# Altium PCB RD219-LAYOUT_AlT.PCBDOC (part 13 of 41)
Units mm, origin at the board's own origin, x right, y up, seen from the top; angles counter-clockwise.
Board outline 209.75 x 159.97 mm, 2 copper layers (TOP, BOTTOM), stack 0 mm thick; 398 components, 199 nets, 1469 pads, 0 vias.
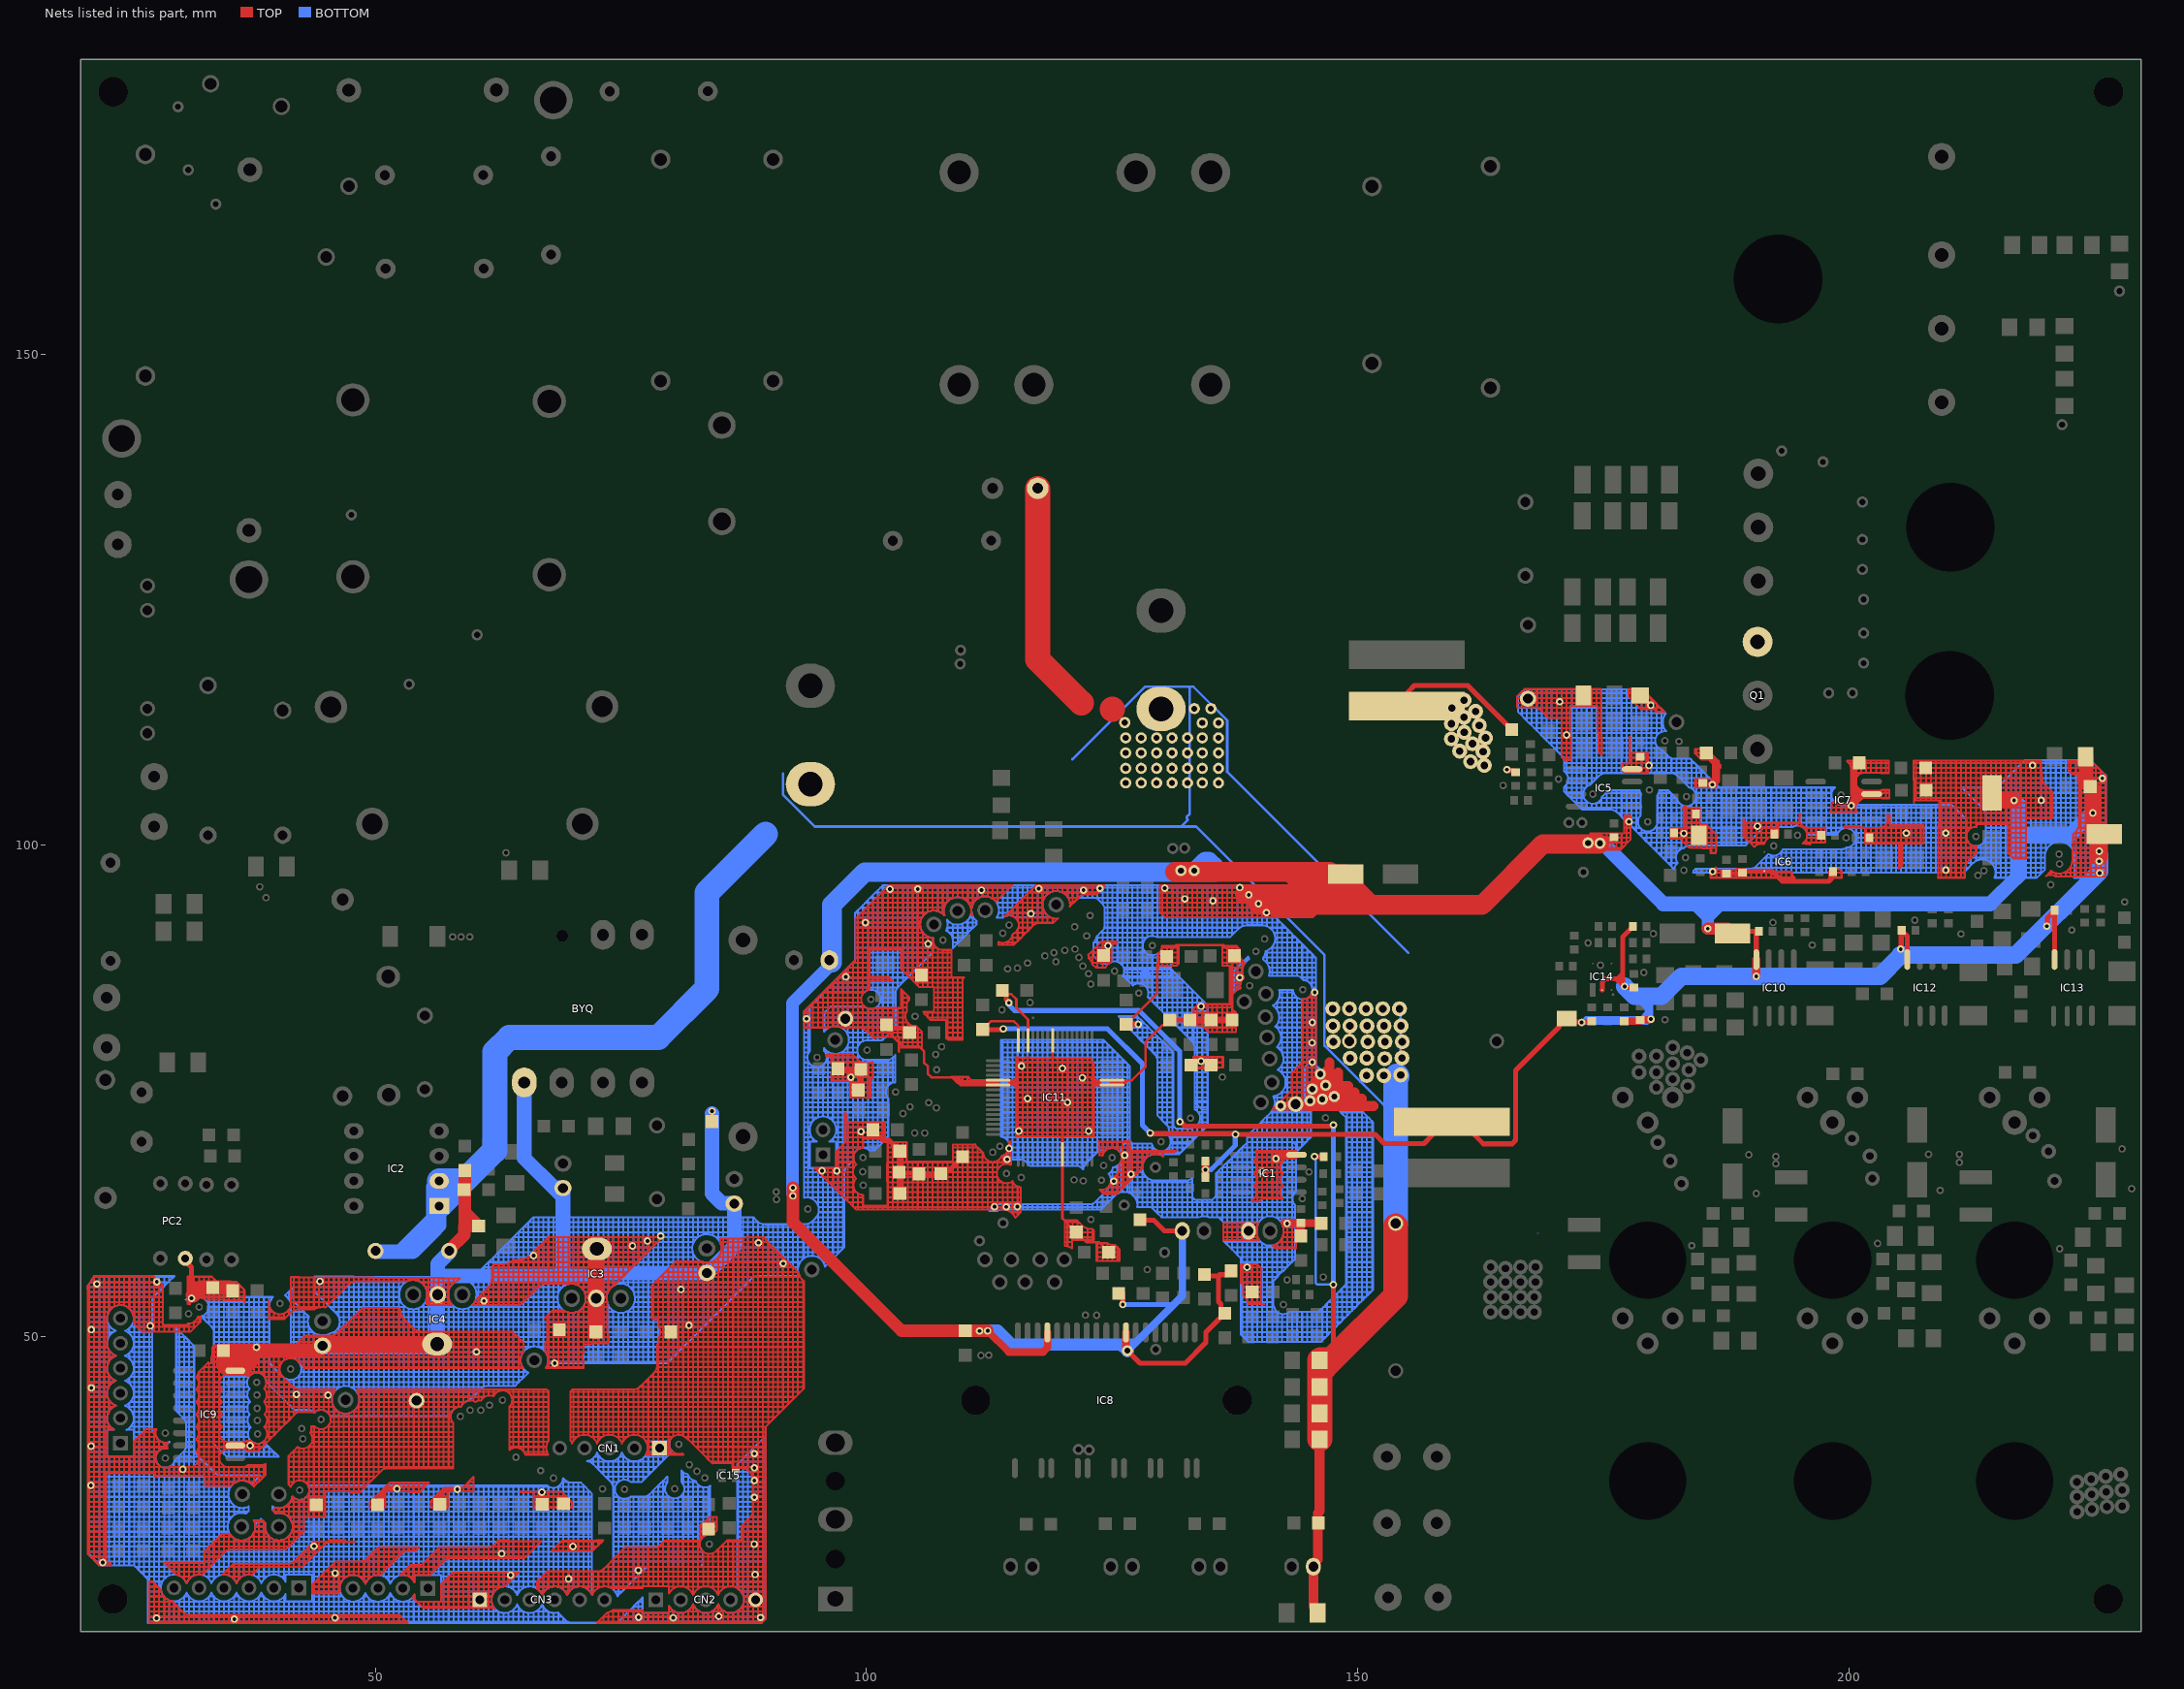
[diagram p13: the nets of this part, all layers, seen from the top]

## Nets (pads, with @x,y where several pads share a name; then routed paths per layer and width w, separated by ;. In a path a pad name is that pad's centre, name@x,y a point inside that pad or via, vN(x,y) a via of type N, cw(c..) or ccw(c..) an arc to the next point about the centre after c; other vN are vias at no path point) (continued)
GND: (continued)
  TOP w0.203: 102.677,80.96 103.185,80.96 ; 102.677,80.96 102.677,81.397 C98.2@102.677,81.468 ; C98.2@102.677,81.468 103.185,81.468 ; C98.2@102.677,81.468 C98.2@102.677,81.976 ; C98.2@102.677,81.976 102.677,82.484 ; C98.2@102.677,81.976 103.185,81.976 ; 102.677,82.484 102.677,82.992 ; 102.677,82.484 103.185,82.484 ; 102.677,82.992 103.185,82.992 ; 102.677,82.992 102.677,83.441 ; 102.677,83.441 103.185,83.441 ; 102.677,89.401 102.677,89.596 ; 102.677,89.401 103.185,89.401 ; 102.677,89.596 102.677,90.104 ; 102.677,89.596 103.185,89.596 ; 102.677,90.104 102.677,90.612 ; 102.677,90.104 103.185,90.104 ; 102.677,90.612 102.677,91.12 ; 102.677,90.612 103.185,90.612 ; 102.677,91.12 102.677,91.628 ; 102.677,91.12 103.185,91.12 ; 102.677,91.628 102.677,92.136 ; 102.677,91.628 103.185,91.628 ; 102.677,92.136 102.677,92.644 ; 102.677,92.136 103.185,92.136 ; 102.677,92.644 102.677,93.152 ; 102.677,92.644 103.185,92.644 ; 102.677,93.152 102.677,93.66 ; 102.677,93.152 103.185,93.152 ; 102.677,93.66 102.677,94.168 ; 102.677,93.66 103.185,93.66 ; 102.677,94.168 102.677,94.676 ; 102.677,94.168 103.185,94.168 ; 102.677,94.676 102.677,95.184 ; 102.677,94.676 103.185,94.676 ; 102.677,95.184 103.185,95.184 ; 102.677,95.184 pad.@102.677,95.692 ; pad.@102.677,95.692 102.677,95.946 ; pad.@102.677,95.692 103.185,95.692 ; 102.677,95.946 103.185,95.946 ; 103.185,62.932 103.185,63.18 ; 103.185,62.932 103.693,62.932 ; 103.185,63.18 103.185,63.688 ; 103.185,63.18 103.693,63.18 ; 103.185,63.688 C72.2@103.185,64.196 ; 103.185,63.688 103.693,63.688 ; C72.2@103.185,64.196 C72.2@103.693,64.196 ; C72.2@103.185,64.196 C72.2@103.185,64.704 ; C72.2@103.185,64.704 103.35,64.704 C72.2@103.693,64.704 ; C72.2@103.185,64.704 C72.2@103.185,65.212 ; C72.2@103.185,65.212 103.35,65.212 C72.2@103.693,65.212 ; C72.2@103.185,65.212 103.185,65.72 ; 103.185,65.72 103.35,65.72 103.693,65.72 ; 103.185,65.72 C73.2@103.185,66.228 ; C73.2@103.185,66.228 103.35,66.228 C73.2@103.693,66.228 ; C73.2@103.185,66.228 C73.2@103.185,66.736 ; C73.2@103.185,66.736 C73.2@103.312,66.736 C73.2@103.693,66.736 ; C73.2@103.185,66.736 C73.2@103.185,67.244 ; C73.2@103.185,67.244 103.185,67.752 ; C73.2@103.185,67.244 103.35,67.244 C73.2@103.693,67.244 ; 103.185,67.752 103.35,67.752 103.693,67.752 ; 103.185,67.752 C70.2@103.185,68.26 ; C70.2@103.185,68.26 103.35,68.26 C70.2@103.693,68.26 ; C70.2@103.185,68.26 C70.2@103.185,68.768 ; C70.2@103.185,68.768 103.35,68.768 C70.2@103.693,68.768 ; C70.2@103.185,68.768 103.185,69.098 C70.2@103.185,69.276 ; C70.2@103.185,69.276 103.185,69.784 ; C70.2@103.185,69.276 C70.2@103.693,69.276 ; 103.185,69.784 103.185,69.802 ; 103.185,69.784 103.693,69.784 ; 103.185,69.802 103.693,69.802 ; 103.185,80.484 103.185,80.96 ; 103.185,80.484 103.294,80.484 103.294,80.452 ; 103.185,80.96 103.185,81.397 103.185,81.468 ; 103.185,80.96 103.693,80.96 ; 103.185,81.468 103.693,81.468 ; 103.185,81.468 103.185,81.976 ; 103.185,81.976 103.185,82.484 ; 103.185,81.976 103.693,81.976 ; 103.185,82.484 103.185,82.992 ; 103.185,82.484 103.693,82.484 ; 103.185,82.992 103.185,83.441 ; 103.185,82.992 103.693,82.992 ; 103.185,83.441 103.517,83.441 103.517,83.5 ; 103.185,89.401 103.185,89.596 ; 103.185,89.401 103.517,89.401 103.517,89.088 ; 103.185,89.596 103.185,90.104 ; 103.185,89.596 103.693,89.596 ; 103.185,90.104 103.185,90.612 ; 103.185,90.104 103.693,90.104 ; 103.185,90.612 103.185,91.12 ; 103.185,90.612 103.693,90.612 ; 103.185,91.12 103.185,91.628 ; 103.185,91.12 103.693,91.12 ; 103.185,91.628 103.185,92.136 ; 103.185,91.628 103.693,91.628 ; 103.185,92.136 103.185,92.644 ; 103.185,92.136 103.693,92.136 ; 103.185,92.644 103.185,93.152 ; 103.185,92.644 103.693,92.644 ; 103.185,93.152 103.185,93.66 ; 103.185,93.152 103.693,93.152 ; 103.185,93.66 103.185,94.168 ; 103.185,93.66 103.693,93.66 ; 103.185,94.168 103.185,94.676 ; 103.185,94.168 103.693,94.168 ; 103.185,94.676 103.185,95.184 ; 103.185,94.676 103.693,94.676 ; 103.185,95.184 103.185,95.692 ; 103.185,95.184 103.693,95.184 ; 103.185,95.692 103.185,95.946 ; 103.185,95.692 103.693,95.692 ; 103.185,95.946 103.693,95.946 ; 103.294,79.436 103.693,79.436 ; 103.294,79.436 103.294,79.913 103.294,79.944 ; 103.294,79.944 103.294,80.452 ; 103.294,79.944 103.693,79.944 ; 103.294,80.452 103.693,80.452 ; 103.517,83.5 103.693,83.5 ; 103.517,83.5 103.517,84.008 ; 103.517,84.008 103.517,84.516 ; 103.517,84.008 103.693,84.008 ; 103.517,84.516 103.517,85.024 ; 103.517,84.516 103.693,84.516 ; 103.517,85.024 103.693,85.024 ; 103.517,85.024 103.517,85.364 103.693,85.187 ; 103.517,87.564 103.517,88.072 ; 103.517,87.564 103.517,87.425 103.693,87.248 ; 103.517,87.564 103.693,87.564 ; 103.517,88.072 103.693,88.072 ; 103.517,88.072 103.517,88.58 ; 103.517,88.58 103.517,89.088 ; 103.517,88.58 103.693,88.58 ; 103.517,89.088 103.693,89.088 ; 103.693,62.932 104.201,62.932 ; 103.693,62.932 103.693,63.18 ; 103.693,63.18 103.693,63.688 ; 103.693,63.18 104.201,63.18 ; 103.693,63.688 C72.2@103.693,64.196 ; 103.693,63.688 104.201,63.688 ; C72.2@103.693,64.196 104.201,64.196 ; C72.2@103.693,64.196 C72.2@103.693,64.704 ; C72.2@103.693,64.704 C72.2@103.693,65.212 ; C72.2@103.693,64.704 104.201,64.704 ; C72.2@103.693,65.212 104.201,65.212 ; C72.2@103.693,65.212 103.693,65.72 ; 103.693,65.72 104.201,65.72 ; 103.693,65.72 C73.2@103.693,66.228 ; C73.2@103.693,66.228 103.693,66.656 C73.2@103.693,66.736 ; C73.2@103.693,66.228 104.201,66.228 ; C73.2@103.693,66.736 104.201,66.736 ; C73.2@103.693,66.736 C73.2@103.693,67.244 ; C73.2@103.693,67.244 103.693,67.752 ; C73.2@103.693,67.244 104.201,67.244 ; 103.693,67.752 104.201,67.752 ; 103.693,67.752 C70.2@103.693,68.26 ; C70.2@103.693,68.26 C70.2@103.693,68.768 ; C70.2@103.693,68.26 104.082,68.26 ; C70.2@103.693,68.768 104.082,68.768 ; C70.2@103.693,68.768 C70.2@103.693,69.276 ; C70.2@103.693,69.276 103.693,69.784 ; C70.2@103.693,69.276 104.082,69.276 ; 103.693,69.784 103.693,69.802 ; 103.693,69.784 104.082,69.784 ; 103.693,69.802 104.082,69.802 104.082,69.784 ; 103.693,79.418 104.201,79.418 ; 103.693,79.418 103.693,79.436 ; 103.693,79.436 104.201,79.436 ; 103.693,79.436 103.693,79.563 103.693,79.944 ; 103.693,79.944 103.693,80.452 ; 103.693,79.944 104.201,79.944 ; 103.693,80.452 C37.1@104.201,80.452 ; 103.693,80.452 103.693,80.96 ; 103.693,80.96 C37.1@104.201,80.96 ; 103.693,80.96 103.693,81.397 103.693,81.468 ; 103.693,81.468 C37.1@104.201,81.468 ; 103.693,81.468 103.693,81.976 ; 103.693,81.976 103.693,82.484 ; 103.693,81.976 104.176,81.976 ; 103.693,82.484 103.693,82.992 ; 103.693,82.484 103.96,82.484 ; 103.693,82.992 103.693,83.5 ; 103.693,82.992 104.035,82.992 ; 103.693,83.5 103.693,84.008 ; 103.693,83.5 104.084,83.5 ; 103.693,84.008 103.693,84.516 ; 103.693,84.008 104.163,84.008 ; 103.693,84.516 104.201,84.516 ; 103.693,84.516 103.693,85.024 ; 103.693,85.024 103.856,85.024 ; 103.693,85.024 103.693,85.187 ; 103.693,85.187 103.856,85.024 ; 103.693,87.248 103.693,87.564 ; 103.693,87.248 103.885,87.056 ; 103.693,87.564 103.693,88.072 ; 103.693,87.564 104.201,87.564 ; 103.693,88.072 103.693,88.58 ; 103.693,88.072 104.201,88.072 ; 103.693,88.58 103.693,89.088 ; 103.693,88.58 104.201,88.58 ; 103.693,89.088 103.693,89.596 ; 103.693,89.088 104.201,89.088 ; 103.693,89.596 103.693,90.104 ; 103.693,89.596 104.201,89.596 ; 103.693,90.104 103.693,90.612 ; 103.693,90.104 104.201,90.104 ; 103.693,90.612 103.693,91.12 ; 103.693,90.612 104.201,90.612 ; 103.693,91.12 103.693,91.628 ; 103.693,91.12 104.201,91.12 ; 103.693,91.628 103.693,92.136 ; 103.693,91.628 104.201,91.628 ; 103.693,92.136 103.693,92.644 ; 103.693,92.136 104.201,92.136 ; 103.693,92.644 103.693,93.152 ; 103.693,92.644 104.201,92.644 ; 103.693,93.152 103.693,93.66 ; 103.693,93.152 104.201,93.152 ; 103.693,93.66 103.693,94.168 ; 103.693,93.66 104.201,93.66 ; 103.693,94.168 103.693,94.676 ; 103.693,94.168 104.201,94.168 ; 103.693,94.676 103.693,95.184 ; 103.693,94.676 104.201,94.676 ; 103.693,95.184 103.693,95.692 ; 103.693,95.184 104.201,95.184 ; 103.693,95.692 103.693,95.946 ; 103.693,95.692 104.201,95.692 ; 103.693,95.946 104.201,95.946 ; 103.856,85.024 104.201,84.679 ; 103.885,87.056 104.201,87.056 ; 103.885,87.056 104.201,86.74 ; 103.96,82.484 ccw(c104.936,82.599) 103.96,82.48 ccw(c104.936,82.599) 104.176,81.976 ; 103.96,82.484 cw(c104.936,82.599) 104.035,82.992 ; 104.035,82.992 cw(c104.936,82.599) 104.084,83.089 ; 104.082,68.26 104.082,68.768 ; 104.082,68.26 104.082,67.814 104.201,67.814 ; 104.082,68.768 104.082,69.276 ; 104.082,69.276 104.082,69.784 ; 104.084,83.089 104.084,83.5 ; 104.084,83.5 104.084,83.65 ; 104.084,83.65 cw(c104.936,83.65) 104.163,84.008 ; 104.084,83.65 cw(c104.936,83.65) 104.163,84.008 ; 104.163,84.008 cw(c104.936,83.65) 104.198,84.076 ; 104.163,84.008 cw(c104.936,83.65) 104.198,84.076 ; 104.176,81.976 ccw(c104.936,82.599) 104.201,81.947 ; 104.198,84.076 cw(c104.936,83.65) 104.201,84.081 ; 104.198,84.076 cw(c104.936,83.65) 104.201,84.081 ; 104.201,62.932 104.709,62.932 ; 104.201,62.932 104.201,63.18 ; 104.201,63.18 104.201,63.688 ; 104.201,63.18 104.709,63.18 ; 104.201,63.688 104.201,64.196 ; 104.201,63.688 104.709,63.688 ; 104.201,64.196 104.201,64.704 ; 104.201,64.196 104.709,64.196 ; 104.201,64.704 104.201,65.212 ; 104.201,64.704 104.709,64.704 ; 104.201,65.212 104.201,65.72 ; 104.201,65.212 104.709,65.212 ; 104.201,65.72 104.201,66.228 ; 104.201,65.72 104.709,65.72 ; 104.201,66.228 104.201,66.656 104.201,66.736 ; 104.201,66.228 C71.2@104.709,66.228 ; 104.201,66.736 104.201,67.244 ; 104.201,66.736 C71.2@104.709,66.736 ; 104.201,67.244 104.201,67.752 ; 104.201,67.244 104.709,67.244 ; 104.201,67.752 104.709,67.752 ; 104.201,67.752 104.201,67.814 ; 104.201,67.814 104.709,67.814 ; 104.201,79.418 104.709,79.418 ; 104.201,79.418 104.201,79.436 ; 104.201,79.436 104.709,79.436 ; 104.201,79.436 104.201,79.563 104.201,79.944 ; 104.201,79.944 C37.1@104.201,80.452 ; 104.201,79.944 104.709,79.944 ; C37.1@104.201,80.452 C37.1@104.201,80.96 ; C37.1@104.201,80.452 C37.1@104.709,80.452 ; C37.1@104.201,80.96 C37.1@104.379,80.96 C37.1@104.709,80.96 ; C37.1@104.201,80.96 104.201,81.138 C37.1@104.201,81.468 ; C37.1@104.201,81.468 104.201,81.947 ; C37.1@104.201,81.468 C37.1@104.709,81.468 ; 104.201,81.947 ccw(c104.936,82.599) 104.205,81.942 ccw(c104.936,82.599) 104.709,81.643 ; 104.201,84.081 cw(c104.936,83.65) 104.333,84.252 ccw(c104.936,83.65) 104.201,84.081 ; 104.201,84.081 104.201,84.516 ; 104.201,84.516 104.201,84.679 ; 104.201,84.516 104.346,84.516 ; 104.201,84.679 104.346,84.534 104.346,84.516 ; 104.201,86.74 104.201,87.056 ; 104.201,87.056 104.201,87.564 ; 104.201,87.056 104.709,87.056 ; 104.201,87.564 104.201,88.072 ; 104.201,87.564 104.709,87.564 ; 104.201,88.072 104.201,88.58 ; 104.201,88.072 104.709,88.072 ; 104.201,88.58 104.201,89.088 ; 104.201,88.58 104.709,88.58 ; 104.201,89.088 104.201,89.596 ; 104.201,89.088 104.709,89.088 ; 104.201,89.596 104.201,90.104 ; 104.201,89.596 104.709,89.596 ; 104.201,90.104 104.201,90.612 ; 104.201,90.104 104.709,90.104 ; 104.201,90.612 104.201,91.12 ; 104.201,90.612 104.709,90.612 ; 104.201,91.12 104.201,91.628 ; 104.201,91.12 104.709,91.12 ; 104.201,91.628 104.201,92.136 ; 104.201,91.628 104.709,91.628 ; 104.201,92.136 104.201,92.644 ; 104.201,92.136 104.709,92.136 ; 104.201,92.644 104.201,93.152 ; 104.201,92.644 104.709,92.644 ; 104.201,93.152 104.201,93.66 ; 104.201,93.152 104.709,93.152 ; 104.201,93.66 104.201,94.168 ; 104.201,93.66 104.709,93.66 ; 104.201,94.168 104.201,94.676 ; 104.201,94.168 104.709,94.168 ; 104.201,94.676 104.201,95.184 ; 104.201,94.676 104.709,94.676 ; 104.201,95.184 104.201,95.692 ; 104.201,95.184 104.709,95.184 ; 104.201,95.692 104.201,95.946 ; 104.201,95.692 104.709,95.692 ; 104.201,95.946 104.709,95.946 ; 104.709,62.932 104.709,63.18 ; 104.709,62.932 105.217,62.932 ; 104.709,63.18 104.709,63.688 ; 104.709,63.18 105.217,63.18 ; 104.709,63.688 104.709,64.196 ; 104.709,63.688 105.217,63.688 ; 104.709,64.196 104.709,64.704 ; 104.709,64.196 105.217,64.196 ; 104.709,64.704 104.709,65.212 ; 104.709,64.704 105.217,64.704 ; 104.709,65.212 104.709,65.72 ; 104.709,65.212 105.217,65.212 ; 104.709,65.72 C71.2@104.709,66.228 ; 104.709,65.72 105.217,65.72 ; C71.2@104.709,66.228 C71.2@105.217,66.228 ; C71.2@104.709,66.228 104.709,66.656 C71.2@104.709,66.736 ; C71.2@104.709,66.736 104.709,67.244 ; C71.2@104.709,66.736 C71.2@105.217,66.736 ; 104.709,67.244 104.709,67.752 ; 104.709,67.244 105.217,67.244 ; 104.709,67.752 104.709,67.814 ; 104.709,67.752 105.217,67.752 ; 104.709,67.814 105.217,67.814 ; 104.709,79.418 104.709,79.436 ; 104.709,79.418 105.217,79.418 ; 104.709,79.436 104.709,79.563 104.709,79.944 ; 104.709,79.436 105.217,79.436 ; 104.709,79.944 C37.1@104.709,80.452 ; 104.709,79.944 105.217,79.944 ; C37.1@104.709,80.452 105.217,80.452 ; C37.1@104.709,80.452 C37.1@104.709,80.96 ; C37.1@104.709,80.96 105.217,80.96 ; C37.1@104.709,80.96 C37.1@104.709,81.468 ; C37.1@104.709,81.468 105.203,81.468 ; C37.1@104.709,81.468 104.709,81.643 ; 104.709,81.643 ccw(c104.936,82.599) 105.048,81.623 ; 104.709,86.232 104.709,86.548 ; 104.709,86.232 104.901,86.04 ; 104.709,86.548 104.709,87.056 ; 104.709,86.548 R66.1@105.217,86.548 ; 104.709,87.056 104.709,87.564 ; 104.709,87.056 R66.1@105.217,87.056 ; 104.709,87.564 104.709,88.072 ; 104.709,87.564 105.217,87.564 ; 104.709,88.072 104.709,88.58 ; 104.709,88.072 105.217,88.072 ; 104.709,88.58 104.709,89.088 ; 104.709,88.58 105.217,88.58 ; 104.709,89.088 104.709,89.596 ; 104.709,89.088 105.217,89.088 ; 104.709,89.596 104.709,90.104 ; 104.709,89.596 105.217,89.596 ; 104.709,90.104 104.709,90.612 ; 104.709,90.104 105.217,90.104 ; 104.709,90.612 104.709,91.12 ; 104.709,90.612 105.217,90.612 ; 104.709,91.12 104.709,91.628 ; 104.709,91.12 105.217,91.12 ; 104.709,91.628 104.709,92.136 ; 104.709,91.628 105.217,91.628 ; 104.709,92.136 104.709,92.644 ; 104.709,92.136 105.217,92.136 ; 104.709,92.644 104.709,93.152 ; 104.709,92.644 105.217,92.644 ; 104.709,93.152 104.709,93.66 ; 104.709,93.152 105.217,93.152 ; 104.709,93.66 104.709,94.168 ; 104.709,93.66 105.217,93.66 ; 104.709,94.168 104.709,94.676 ; 104.709,94.168 105.217,94.168 ; 104.709,94.676 104.709,95.184 ; 104.709,94.676 105.217,94.676 ; 104.709,95.184 104.709,95.692 ; 104.709,95.184 105.217,95.184 ; 104.709,95.692 104.709,95.946 ; 104.709,95.692 pad.@105.217,95.692 ; 104.709,95.946 105.217,95.946 ; 104.901,86.04 105.217,86.04 ; 104.901,86.04 105.217,85.724 ; 105.048,81.623 105.203,81.468 ; 105.203,81.468 105.217,81.454 ; 105.217,62.932 105.217,63.18 ; 105.217,62.932 105.725,62.932 ; 105.217,63.18 105.217,63.688 ; 105.217,63.18 105.725,63.18 ; 105.217,63.688 105.217,64.196 ; 105.217,63.688 105.725,63.688 ; 105.217,64.196 105.217,64.704 ; 105.217,64.196 105.725,64.196 ; 105.217,64.704 105.217,65.212 ; 105.217,64.704 105.725,64.704 ; 105.217,65.212 105.217,65.72 ; 105.217,65.212 105.725,65.212 ; 105.217,65.72 C71.2@105.217,66.228 ; 105.217,65.72 105.725,65.72 ; C71.2@105.217,66.228 105.217,66.656 C71.2@105.217,66.736 ; C71.2@105.217,66.228 C71.2@105.725,66.228 ; C71.2@105.217,66.736 105.217,67.244 ; C71.2@105.217,66.736 C71.2@105.725,66.736 ; 105.217,67.244 105.217,67.752 ; 105.217,67.244 105.725,67.244 ; 105.217,67.752 105.217,67.814 ; 105.217,67.752 105.725,67.752 ; 105.217,67.814 105.725,67.814 ; 105.217,79.418 105.217,79.436 ; 105.217,79.418 105.489,79.418 105.631,79.418 105.631,79.436 ; 105.217,79.436 105.217,79.563 105.217,79.944 ; 105.217,79.436 105.471,79.436 105.631,79.436 ; 105.217,79.944 105.217,80.452 ; 105.217,79.944 105.616,79.944 ; 105.217,80.452 105.616,80.452 ; 105.217,80.452 105.217,80.96 ; 105.217,80.96 105.616,80.96 ; 105.217,80.96 105.217,81.454 ; 105.217,81.454 105.616,81.054 105.616,80.96 ; 105.217,85.724 105.217,86.04 ; 105.217,85.724 105.377,85.564 105.725,85.564 ; 105.217,86.04 R66.1@105.217,86.548 ; 105.217,86.04 105.725,86.04 ; R66.1@105.217,86.548 R66.1@105.725,86.548 ; R66.1@105.217,86.548 R66.1@105.217,87.056 ; R66.1@105.217,87.056 105.217,87.564 ; R66.1@105.217,87.056 R66.1@105.725,87.056 ; 105.217,87.564 105.217,88.072 ; 105.217,87.564 105.725,87.564 ; 105.217,88.072 105.217,88.58 ; 105.217,88.072 105.725,88.072 ; 105.217,88.58 105.217,89.088 ; 105.217,88.58 105.725,88.58 ; 105.217,89.088 105.217,89.596 ; 105.217,89.088 105.725,89.088 ; 105.217,89.596 105.217,90.104 ; 105.217,89.596 105.725,89.596 ; 105.217,90.104 105.217,90.612 ; 105.217,90.104 105.725,90.104 ; 105.217,90.612 105.217,91.12 ; 105.217,90.612 105.725,90.612 ; 105.217,91.12 105.725,91.12 ; 105.217,91.12 105.217,91.628 ; 105.217,91.628 105.217,92.136 ; 105.217,91.628 105.498,91.628 ; 105.217,92.136 105.217,92.644 ; 105.217,92.136 105.467,92.136 ccw(c106.858,91.966) 105.498,91.628 ; 105.217,92.644 105.217,93.152 ; 105.217,92.644 105.631,92.644 ; 105.217,93.152 105.217,93.66 ; 105.217,93.152 105.725,93.152 ; 105.217,93.66 105.725,93.66 ; 105.217,93.66 105.217,94.168 ; 105.217,94.168 105.217,94.676 ; 105.217,94.168 105.725,94.168 ; 105.217,94.676 105.217,95.184 ; 105.217,94.676 105.725,94.676 ; 105.217,95.184 pad.@105.217,95.565 pad.@105.217,95.692 ; 105.217,95.184 105.725,95.184 ; pad.@105.217,95.692 105.217,95.946 ; pad.@105.217,95.692 105.725,95.692 ; 105.217,95.946 105.725,95.946 ; 105.616,79.944 105.616,80.452 ; 105.616,80.452 105.616,80.96 ; 105.631,92.644 cw(c106.858,91.966) 105.725,92.791 ; 105.725,62.932 106.233,62.932 ; 105.725,62.932 105.725,63.18 ; 105.725,63.18 105.725,63.688 ; 105.725,63.18 106.233,63.18 ; 105.725,63.688 105.725,64.196 ; 105.725,63.688 106.233,63.688 ; 105.725,64.196 105.725,64.704 ; 105.725,64.196 106.233,64.196 ; 105.725,64.704 105.725,65.212 ; 105.725,64.704 106.233,64.704 ; 105.725,65.212 106.233,65.212 ; 105.725,65.212 105.725,65.72 ; 105.725,65.72 106.233,65.72 ; 105.725,65.72 C71.2@105.725,66.228 ; C71.2@105.725,66.228 106.233,66.228 ; C71.2@105.725,66.228 105.725,66.592 C71.2@105.725,66.736 ; C71.2@105.725,66.736 105.725,67.244 ; C71.2@105.725,66.736 106.233,66.736 ; 105.725,67.244 105.725,67.752 ; 105.725,67.244 106.233,67.244 ; 105.725,67.752 106.233,67.752 ; 105.725,67.752 105.725,67.814 ; 105.725,67.814 106.233,67.814 ; 105.725,85.564 105.725,86.04 ; 105.725,85.564 106.233,85.564 ; 105.725,86.04 R66.1@105.725,86.548 ; 105.725,86.04 106.233,86.04 ; R66.1@105.725,86.548 R66.1@106.233,86.548 ; R66.1@105.725,86.548 R66.1@105.725,87.056 ; R66.1@105.725,87.056 105.725,87.564 ; R66.1@105.725,87.056 R66.1@106.233,87.056 ; 105.725,87.564 105.725,88.072 ; 105.725,87.564 106.233,87.564 ; 105.725,88.072 105.725,88.58 ; 105.725,88.072 106.233,88.072 ; 105.725,88.58 105.725,89.088 ; 105.725,88.58 106.233,88.58 ; 105.725,89.088 105.725,89.596 ; 105.725,89.088 106.233,89.088 ; 105.725,89.596 105.725,90.104 ; 105.725,89.596 106.233,89.596 ; 105.725,90.104 105.725,90.612 ; 105.725,90.104 pad.@106.233,90.104 ; 105.725,90.612 105.725,91.12 ; 105.725,90.612 106.233,90.612 ; 105.725,91.12 105.741,91.12 ; 105.725,91.12 105.725,91.142 ccw(c106.858,91.966) 105.741,91.12 ; 105.725,92.791 cw(c106.858,91.966) 106.111,93.152 ; 105.725,92.791 105.725,93.152 ; 105.725,93.152 105.725,93.66 ; 105.725,93.152 106.111,93.152 ; 105.725,93.66 106.233,93.66 ; 105.725,93.66 105.725,94.168 ; 105.725,94.168 105.725,94.676 ; 105.725,94.168 106.233,94.168 ; 105.725,94.676 105.725,95.184 ; 105.725,94.676 106.233,94.676 ; 105.725,95.184 105.725,95.692 ; 105.725,95.184 106.233,95.184 ; 105.725,95.692 105.725,95.946 ; 105.725,95.692 106.233,95.692 ; 105.725,95.946 106.233,95.946 ; 105.836,82.992 cw(c104.936,82.599) 105.887,82.844 ; 105.836,82.992 106.233,82.992 ; 105.887,82.844 106.233,82.498 ; 106.111,93.152 cw(c106.858,91.966) 106.116,93.155 cw(c106.858,91.966) 106.233,93.221 ; 106.233,62.932 106.741,62.932 ; 106.233,62.932 106.233,63.18 ; 106.233,63.18 106.233,63.688 ; 106.233,63.18 106.741,63.18 ; 106.233,63.688 106.233,64.196 ; 106.233,63.688 106.741,63.688 ; 106.233,64.196 106.233,64.704 ; 106.233,64.196 106.741,64.196 ; 106.233,64.704 106.233,65.212 ; 106.233,64.704 106.741,64.704 ; 106.233,65.212 106.741,65.212 ; 106.233,65.212 106.233,65.72 ; 106.233,65.72 106.741,65.72 ; 106.233,65.72 106.233,66.228 ; 106.233,66.228 106.741,66.228 ; 106.233,66.228 106.233,66.592 106.233,66.736 ; 106.233,66.736 106.233,67.244 ; 106.233,66.736 106.741,66.736 ; 106.233,67.244 106.233,67.752 ; 106.233,67.244 106.741,67.244 ; 106.233,67.752 106.741,67.752 ; 106.233,67.752 106.233,67.814 ; 106.233,82.498 106.247,82.484 ; 106.233,82.498 106.233,82.992 ; 106.233,82.992 106.741,82.992 ; 106.233,82.992 106.233,83.061 ; 106.233,83.061 106.741,83.061 ; 106.233,85.564 106.741,85.564 ; 106.233,85.564 106.233,86.04 ; 106.233,86.04 R66.1@106.233,86.548 ; 106.233,86.04 106.741,86.04 ; R66.1@106.233,86.548 106.741,86.548 ; R66.1@106.233,86.548 R66.1@106.233,87.056 ; R66.1@106.233,87.056 106.233,87.564 ; R66.1@106.233,87.056 106.741,87.056 ; 106.233,87.564 106.741,87.564 ; 106.233,87.564 106.233,88.072 ; 106.233,88.072 106.233,88.58 ; 106.233,88.072 106.741,88.072 ; 106.233,88.58 106.233,89.088 ; 106.233,88.58 106.741,88.58 ; 106.233,89.088 106.741,89.088 ; 106.233,89.088 106.233,89.596 ; 106.233,89.596 pad.@106.233,90.104 ; 106.233,89.596 106.741,89.596 ; pad.@106.233,90.104 106.233,90.612 ; pad.@106.233,90.104 106.741,90.104 ; 106.233,90.612 106.498,90.612 ; 106.233,93.221 cw(c106.858,91.966) 106.736,93.363 cw(c106.858,91.966) 106.741,93.363 ; 106.233,93.221 106.233,93.66 ; 106.233,93.66 106.233,94.168 ; 106.233,93.66 106.741,93.66 ; 106.233,94.168 106.233,94.676 ; 106.233,94.168 106.741,94.168 ; 106.233,94.676 106.233,95.184 ; 106.233,94.676 106.741,94.676 ; 106.233,95.184 106.233,95.692 ; 106.233,95.184 106.741,95.184 ; 106.233,95.692 106.233,95.946 ; 106.233,95.692 106.741,95.692 ; 106.233,95.946 106.741,95.946 ; 106.247,82.484 106.741,82.484 ; 106.247,82.484 106.52,82.212 106.741,82.212 ; 106.498,90.612 ccw(c106.858,91.966) 106.741,90.57 ; 106.741,62.932 107.249,62.932 ; 106.741,62.932 106.741,63.18 ; 106.741,63.18 106.741,63.688 ; 106.741,63.18 107.249,63.18 ; 106.741,63.688 106.741,64.196 ; 106.741,63.688 107.249,63.688 ; 106.741,64.196 106.741,64.704 ; 106.741,64.196 107.249,64.196 ; 106.741,64.704 106.741,65.212 ; 106.741,64.704 107.249,64.704 ; 106.741,65.212 107.249,65.212 ; 106.741,65.212 106.741,65.72 ; 106.741,65.72 107.249,65.72 ; 106.741,65.72 106.741,66.228 ; 106.741,66.228 C69.2@107.249,66.228 ; 106.741,66.228 106.741,66.592 106.741,66.736 ; 106.741,66.736 106.741,67.244 ; 106.741,66.736 C69.2@107.249,66.736 ; 106.741,67.244 106.741,67.752 ; 106.741,67.244 C69.2@107.249,67.244 ; 106.741,67.752 107.249,67.752 ; 106.741,67.752 106.741,67.846 ; 106.741,67.846 107.249,67.846 ; 106.741,82.212 107.249,82.212 ; 106.741,82.212 106.741,82.484 ; 106.741,82.484 106.741,82.992 ; 106.741,82.484 107.249,82.484 ; 106.741,82.992 107.249,82.992 ; 106.741,82.992 106.741,83.061 ; 106.741,83.061 106.85,83.061 106.85,83.5 ; 106.741,85.564 106.85,85.564 106.85,85.532 ; 106.741,85.564 106.741,86.04 ; 106.741,86.04 106.741,86.548 ; 106.741,86.04 107.249,86.04 ; 106.741,86.548 107.249,86.548 ; 106.741,86.548 106.741,87.056 ; 106.741,87.056 106.741,87.564 ; 106.741,87.056 107.249,87.056 ; 106.741,87.564 106.741,88.072 ; 106.741,87.564 107.249,87.564 ; 106.741,88.072 106.741,88.58 ; 106.741,88.072 107.249,88.072 ; 106.741,88.58 106.741,89.088 ; 106.741,88.58 107.249,88.58 ; 106.741,89.088 106.741,89.596 ; 106.741,89.088 107.249,89.088 ; 106.741,89.596 107.132,89.596 ; 106.741,89.596 106.741,90.104 ; 106.741,90.104 106.741,90.57 ; 106.741,93.363 cw(c106.858,91.966) 107.245,93.314 cw(c106.858,91.966) 107.249,93.313 ; 106.741,93.363 106.741,93.66 ; 106.741,93.66 106.741,94.168 ; 106.741,93.66 107.249,93.66 ; 106.741,94.168 106.741,94.676 ; 106.741,94.168 107.249,94.168 ; 106.741,94.676 106.741,95.184 ; 106.741,94.676 107.249,94.676 ; 106.741,95.184 106.741,95.692 ; 106.741,95.184 107.249,95.184 ; 106.741,95.692 106.741,95.946 ; 106.741,95.692 107.249,95.692 ; 106.741,95.946 107.249,95.946 ; 106.85,83.5 107.249,83.5 ; 106.85,83.5 106.85,84.008 ; 106.85,84.008 107.249,84.008 ; 106.85,84.008 106.85,84.516 ; 106.85,84.516 107.249,84.516 ; 106.85,84.516 106.85,85.024 ; 106.85,85.024 106.85,85.532 ; 106.85,85.024 107.249,85.024 ; 106.85,85.532 107.249,85.532 ; 107.132,89.596 ccw(c107.777,90.362) 107.247,89.513 ccw(c107.777,90.362) 107.249,89.511 ; 107.249,62.932 107.249,63.18 ; 107.249,62.932 107.757,62.932 ; 107.249,63.18 107.249,63.688 ; 107.249,63.18 107.757,63.18 ; 107.249,63.688 107.249,64.196 ; 107.249,63.688 107.757,63.688 ; 107.249,64.196 107.249,64.704 ; 107.249,64.196 107.757,64.196 ; 107.249,64.704 107.249,65.212 ; 107.249,64.704 107.757,64.704 ; 107.249,65.212 107.249,65.72 ; 107.249,65.212 107.757,65.212 ; 107.249,65.72 C69.2@107.249,66.228 ; 107.249,65.72 107.757,65.72 ; C69.2@107.249,66.228 107.249,66.592 C69.2@107.249,66.736 ; C69.2@107.249,66.228 C69.2@107.757,66.228 ; C69.2@107.249,66.736 C69.2@107.249,67.244 ; C69.2@107.249,66.736 107.677,66.736 C69.2@107.757,66.736 ; C69.2@107.249,67.244 107.249,67.752 ; C69.2@107.249,67.244 C69.2@107.757,67.244 ; 107.249,67.752 107.249,67.846 ; 107.249,67.752 107.757,67.752 ; 107.249,67.846 107.757,67.846 ; 107.249,82.212 107.757,82.212 ; 107.249,82.212 107.249,82.484 ; 107.249,82.484 107.249,82.992 ; 107.249,82.484 107.757,82.484 ; 107.249,82.992 107.757,82.992 ; 107.249,82.992 107.249,83.5 ; 107.249,83.5 107.249,84.008 ; 107.249,83.5 107.757,83.5 ; 107.249,84.008 107.249,84.516 ; 107.249,84.008 107.757,84.008 ; 107.249,84.516 107.249,85.024 ; 107.249,84.516 107.757,84.516 ; 107.249,85.024 107.249,85.532 ; 107.249,85.024 107.757,85.024 ; 107.249,85.532 107.757,85.532 ; 107.249,85.532 107.249,86.04 ; 107.249,86.04 107.249,86.548 ; 107.249,86.04 107.757,86.04 ; 107.249,86.548 107.757,86.548 ; 107.249,86.548 107.249,87.056 ; 107.249,87.056 107.249,87.564 ; 107.249,87.056 107.757,87.056 ; 107.249,87.564 107.757,87.564 ; 107.249,87.564 107.249,88.072 ; 107.249,88.072 107.249,88.58 ; 107.249,88.072 107.757,88.072 ; 107.249,88.58 107.249,89.088 ; 107.249,88.58 107.757,88.58 ; 107.249,89.088 107.757,89.088 ; 107.249,89.088 107.249,89.511 ; 107.249,89.511 ccw(c107.777,90.362) 107.757,89.361 ; 107.249,93.313 cw(c106.858,91.966) 107.606,93.152 ; 107.249,93.313 107.249,93.66 ; 107.249,93.66 107.249,94.168 ; 107.249,93.66 107.757,93.66 ; 107.249,94.168 107.249,94.676 ; 107.249,94.168 107.757,94.168 ; 107.249,94.676 107.249,95.184 ; 107.249,94.676 107.757,94.676 ; 107.249,95.184 107.249,95.692 ; 107.249,95.184 107.757,95.184 ; 107.249,95.692 107.249,95.946 ; 107.249,95.692 107.757,95.692 ; 107.249,95.946 107.757,95.946 ; 107.606,93.152 cw(c106.858,91.966) 107.757,93.042 ; 107.606,93.152 107.757,93.152 ; 107.757,62.932 107.757,63.18 ; 107.757,62.932 108.265,62.932 ; 107.757,63.18 107.757,63.688 ; 107.757,63.18 108.265,63.18 ; 107.757,63.688 107.757,64.196 ; 107.757,63.688 108.265,63.688 ; 107.757,64.196 107.757,64.704 ; 107.757,64.196 108.265,64.196 ; 107.757,64.704 107.757,65.212 ; 107.757,64.704 108.265,64.704 ; 107.757,65.212 107.757,65.72 ; 107.757,65.212 108.265,65.212 ; 107.757,65.72 C69.2@107.757,66.228 ; 107.757,65.72 108.265,65.72 ; C69.2@107.757,66.228 108.265,66.228 ; C69.2@107.757,66.228 C69.2@107.757,66.736 ; C69.2@107.757,66.736 107.757,66.816 C69.2@107.757,67.244 ; C69.2@107.757,66.736 108.265,66.736 ; C69.2@107.757,67.244 107.757,67.752 ; C69.2@107.757,67.244 108.265,67.244 ; 107.757,67.752 107.757,67.846 ; 107.757,67.752 108.265,67.752 ; 107.757,67.846 108.265,67.846 ; 107.757,82.212 108.12,82.212 108.12,81.976 ; 107.757,82.212 107.757,82.484 ; 107.757,82.484 107.757,82.992 ; 107.757,82.484 108.265,82.484 ; 107.757,82.992 107.757,83.5 ; 107.757,82.992 108.265,82.992 ; 107.757,83.5 107.757,84.008 ; 107.757,83.5 108.265,83.5 ; 107.757,84.008 107.757,84.516 ; 107.757,84.008 108.265,84.008 ; 107.757,84.516 107.757,85.024 ; 107.757,84.516 108.265,84.516 ; 107.757,85.024 107.757,85.532 ; 107.757,85.024 108.265,85.024 ; 107.757,85.532 108.265,85.532 ; 107.757,85.532 107.757,86.04 ; 107.757,86.04 107.757,86.548 ; 107.757,86.04 108.265,86.04 ; 107.757,86.548 107.757,87.056 ; 107.757,86.548 108.265,86.548 ; 107.757,87.056 107.757,87.564 ; 107.757,87.056 108.265,87.056 ; 107.757,87.564 107.757,88.072 ; 107.757,87.564 108.265,87.564 ; 107.757,88.072 107.757,88.58 ; 107.757,88.072 108.265,88.072 ; 107.757,88.58 107.757,89.088 ; 107.757,88.58 108.265,88.58 ; 107.757,89.088 108.265,89.088 ; 107.757,89.088 107.757,89.361 ; 107.757,89.361 ccw(c107.777,90.362) 107.777,89.361 108.265,89.361 ; 107.757,93.042 107.757,93.152 ; 107.757,93.152 107.757,93.66 ; 107.757,93.152 107.867,93.152 ; 107.757,93.66 107.757,94.168 ; 107.757,93.66 107.897,93.66 ; 107.757,94.168 107.757,94.676 ; 107.757,94.168 108.138,94.168 ; 107.757,94.676 107.757,95.184 ; 107.757,94.676 108.265,94.676 ; 107.757,95.184 107.757,95.692 ; 107.757,95.184 108.265,95.184 ; 107.757,95.692 107.757,95.946 ; 107.757,95.692 108.265,95.692 ; 107.757,95.946 108.265,95.946 ; 107.867,93.152 cw(c109.258,93.325) 107.897,93.66 ; 107.897,93.66 cw(c109.258,93.325) 108.138,94.168 ; 108.12,80.363 cw(c107.639,79.506) 108.265,80.263 ; 108.12,80.363 108.12,80.452 ; 108.12,80.452 108.12,80.96 ; 108.12,80.452 108.265,80.452 ; 108.12,80.96 108.265,80.96 ; 108.12,80.96 108.12,81.468 ; 108.12,81.468 108.265,81.468 ; 108.12,81.468 108.12,81.976 ; 108.12,81.976 108.265,81.976 ; 108.138,94.168 cw(c109.258,93.325) 108.265,94.314 ; 108.265,62.932 108.773,62.932 ; 108.265,62.932 108.265,63.18 ; 108.265,63.18 108.265,63.688 ; 108.265,63.18 108.773,63.18 ; 108.265,63.688 108.265,64.196 ; 108.265,63.688 108.773,63.688 ; 108.265,64.196 108.265,64.704 ; 108.265,64.196 108.773,64.196 ; 108.265,64.704 108.265,65.212 ; 108.265,64.704 108.773,64.704 ; 108.265,65.212 108.773,65.212 ; 108.265,65.212 108.265,65.72 ; 108.265,65.72 108.773,65.72 ; 108.265,65.72 108.265,66.228 ; 108.265,66.228 108.773,66.228 ; 108.265,66.228 108.265,66.736 ; 108.265,66.736 108.265,67.004 108.265,67.244 ; 108.265,66.736 108.773,66.736 ; 108.265,67.244 108.265,67.752 ; 108.265,67.244 108.722,67.244 108.773,67.244 ; 108.265,67.752 108.773,67.752 ; 108.265,67.752 108.265,67.846 ; 108.265,67.846 108.773,67.846 ; 108.265,80.263 108.265,80.452 ; 108.265,80.452 108.773,80.452 ; 108.265,80.452 108.265,80.96 ; 108.265,80.96 108.265,81.468 ; 108.265,80.96 108.773,80.96 ; 108.265,81.468 108.265,81.976 ; 108.265,81.468 108.773,81.468 ; 108.265,81.976 108.265,82.484 ; 108.265,81.976 108.773,81.976 ; 108.265,82.484 108.265,82.992 ; 108.265,82.484 108.773,82.484 ; 108.265,82.992 108.265,83.5 ; 108.265,82.992 108.773,82.992 ; 108.265,83.5 108.265,84.008 ; 108.265,83.5 108.773,83.5 ; 108.265,84.008 108.265,84.516 ; 108.265,84.008 108.773,84.008 ; 108.265,84.516 108.265,85.024 ; 108.265,84.516 108.773,84.516 ; 108.265,85.024 108.265,85.532 ; 108.265,85.024 108.773,85.024 ; 108.265,85.532 108.265,86.04 ; 108.265,85.532 108.773,85.532 ; 108.265,86.04 108.265,86.548 ; 108.265,86.04 108.773,86.04 ; 108.265,86.548 108.265,87.056 ; 108.265,86.548 108.773,86.548 ; 108.265,87.056 108.265,87.564 ; 108.265,87.056 108.664,87.056 ; 108.265,87.564 108.265,88.072 ; 108.265,87.564 108.664,87.564 ; 108.265,88.072 108.265,88.58 ; 108.265,88.072 108.664,88.072 ; 108.265,88.58 108.265,89.088 ; 108.265,88.58 108.664,88.58 ; 108.265,89.088 108.265,89.361 ; 108.265,89.088 108.664,89.088 ; 108.265,89.361 108.664,89.361 108.664,89.088 ; 108.265,94.314 cw(c109.258,93.325) 108.267,94.316 cw(c109.258,93.325) 108.773,94.64 ; 108.265,94.314 108.265,94.676 ; 108.265,94.676 108.773,94.676 ; 108.265,94.676 108.265,95.184 ; 108.265,95.184 108.265,95.692 ; 108.265,95.184 108.773,95.184 ; 108.265,95.692 108.265,95.946 ; 108.265,95.692 108.773,95.692 ; 108.265,95.946 108.773,95.946 ; 108.66,76.388 108.773,76.388 ; 108.66,76.388 109.168,75.88 ; 108.664,87.056 108.664,87.564 ; 108.664,87.056 108.664,86.566 108.773,86.566 ; 108.664,87.564 108.664,88.072 ; 108.664,88.072 108.664,88.58 ; 108.773,62.932 109.281,62.932 ; 108.773,62.932 108.773,63.18 ; 108.773,63.18 108.773,63.688 ; 108.773,63.18 109.281,63.18 ; 108.773,63.688 108.773,64.196 ; 108.773,63.688 109.281,63.688 ; 108.773,64.196 108.773,64.704 ; 108.773,64.196 109.281,64.196 ; 108.773,64.704 108.773,65.212 ; 108.773,64.704 109.281,64.704 ; 108.773,65.212 108.773,65.72 ; 108.773,65.212 109.281,65.212 ; 108.773,65.72 108.773,66.228 ; 108.773,65.72 109.281,65.72 ; 108.773,66.228 108.773,66.736 ; 108.773,66.228 109.281,66.228 ; 108.773,66.736 108.773,67.244 ; 108.773,66.736 109.281,66.736 ; 108.773,67.244 108.773,67.295 108.773,67.752 ; 108.773,67.244 109.281,67.244 ; 108.773,67.752 109.23,67.752 C28.2@109.281,67.752 ; 108.773,67.752 108.773,67.846 ; 108.773,67.846 108.801,67.846 108.801,68.26 ; 108.773,76.388 109.027,76.388 109.281,76.388 ; 108.773,76.388 108.773,76.445 ; 108.773,76.445 109.281,76.445 ; 108.773,80.234 109.281,80.234 ; 108.773,80.234 108.773,80.452 ; 108.773,80.452 108.773,80.96 ; 108.773,80.452 109.281,80.452 ; 108.773,80.96 108.773,81.468 ; 108.773,80.96 109.281,80.96 ; 108.773,81.468 108.773,81.976 ; 108.773,81.468 109.281,81.468 ; 108.773,81.976 108.773,82.484 ; 108.773,81.976 109.281,81.976 ; 108.773,82.484 108.773,82.992 ; 108.773,82.484 109.281,82.484 ; 108.773,82.992 108.773,83.5 ; 108.773,82.992 109.281,82.992 ; 108.773,83.5 108.773,84.008 ; 108.773,83.5 109.281,83.5 ; 108.773,84.008 108.773,84.516 ; 108.773,84.008 109.281,84.008 ; 108.773,84.516 108.773,85.024 ; 108.773,84.516 109.281,84.516 ; 108.773,85.024 108.773,85.532 ; 108.773,85.024 109.281,85.024 ; 108.773,85.532 108.773,86.04 ; 108.773,85.532 109.281,85.532 ; 108.773,86.04 108.773,86.548 ; 108.773,86.04 109.281,86.04 ; 108.773,86.548 108.773,86.566 ; 108.773,86.548 109.281,86.548 ; 108.773,86.566 109.281,86.566 ; 108.773,94.64 cw(c109.258,93.325) 108.779,94.642 cw(c109.258,93.325) 108.885,94.676 ; 108.773,94.64 108.773,94.676 ; 108.773,94.676 108.773,95.184 ; 108.773,94.676 108.885,94.676 ; 108.773,95.184 108.773,95.692 ; 108.773,95.184 109.281,95.184 ; 108.773,95.692 108.773,95.946 ; 108.773,95.692 109.281,95.692 ; 108.773,95.946 109.281,95.946 ; 108.801,68.26 108.801,68.768 ; 108.801,68.26 C28.2@109.281,68.26 ; 108.801,68.768 108.801,69.276 ; 108.801,68.768 C28.2@109.281,68.768 ; 108.801,69.276 108.801,69.548 109.281,69.548 ; 108.801,69.276 109.281,69.276 ; 108.885,94.676 cw(c109.258,93.325) 109.281,94.726 ; 109.168,75.88 109.214,75.835 109.281,75.835 ; 109.168,75.88 109.281,75.88 ; 109.281,62.932 109.281,63.18 ; 109.281,62.932 109.789,62.932 ; 109.281,63.18 109.281,63.688 ; 109.281,63.18 109.789,63.18 ; 109.281,63.688 109.281,64.196 ; 109.281,63.688 109.789,63.688 ; 109.281,64.196 109.281,64.704 ; 109.281,64.196 109.789,64.196 ; 109.281,64.704 109.281,65.212 ; 109.281,64.704 109.789,64.704 ; 109.281,65.212 109.281,65.72 ; 109.281,65.212 109.789,65.212 ; 109.281,65.72 109.281,66.228 ; 109.281,65.72 109.789,65.72 ; 109.281,66.228 109.281,66.736 ; 109.281,66.228 109.789,66.228 ; 109.281,66.736 109.281,67.244 ; 109.281,66.736 109.789,66.736 ; 109.281,67.244 C28.2@109.281,67.752 ; 109.281,67.244 109.789,67.244 ; C28.2@109.281,67.752 109.281,67.803 C28.2@109.281,68.26 ; C28.2@109.281,67.752 C28.2@109.789,67.752 ; C28.2@109.281,68.26 109.738,68.26 C28.2@109.789,68.26 ; C28.2@109.281,68.26 C28.2@109.281,68.768 ; C28.2@109.281,68.768 109.281,69.276 ; C28.2@109.281,68.768 C28.2@109.789,68.768 ; 109.281,69.276 109.281,69.548 ; 109.281,69.276 109.789,69.276 ; 109.281,69.548 109.789,69.548 ; 109.281,75.835 109.281,75.88 ; 109.281,75.835 109.326,75.835 109.789,75.835 ; 109.281,75.88 109.281,76.007 109.281,76.134 109.281,76.388 ; 109.281,75.88 109.789,75.88 ; 109.281,76.388 109.789,76.388 ; 109.281,76.388 109.281,76.445 ; 109.281,76.445 109.789,76.445 ; 109.281,80.234 109.789,80.234 ; 109.281,80.234 109.281,80.452 ; 109.281,80.452 109.789,80.452 ; 109.281,80.452 109.281,80.96 ; 109.281,80.96 109.789,80.96 ; 109.281,80.96 109.281,81.468 ; 109.281,81.468 109.789,81.468 ; 109.281,81.468 109.281,81.976 ; 109.281,81.976 109.789,81.976 ; 109.281,81.976 109.281,82.484 ; 109.281,82.484 109.789,82.484 ; 109.281,82.484 109.281,82.992 ; 109.281,82.992 109.789,82.992 ; 109.281,82.992 109.281,83.5 ; 109.281,83.5 109.789,83.5 ; 109.281,83.5 109.281,84.008 ; 109.281,84.008 109.789,84.008 ; 109.281,84.008 109.281,84.516 ; 109.281,84.516 109.789,84.516 ; 109.281,84.516 109.281,85.024 ; 109.281,85.024 109.789,85.024 ; 109.281,85.024 109.281,85.532 ; 109.281,85.532 109.789,85.532 ; 109.281,85.532 109.281,86.04 ; 109.281,86.04 109.789,86.04 ; 109.281,86.04 109.281,86.548 ; 109.281,86.548 109.789,86.548 ; 109.281,86.548 109.281,86.566 ; 109.281,86.566 109.789,86.566 ; 109.281,94.726 cw(c109.258,93.325) 109.283,94.726 cw(c109.258,93.325) 109.631,94.676 ; 109.281,94.726 109.281,95.184 ; 109.281,95.184 109.281,95.692 ; 109.281,95.184 109.789,95.184 ; 109.281,95.692 109.281,95.946 ; 109.281,95.692 109.789,95.692 ; 109.281,95.946 109.789,95.946 ; 109.631,94.676 cw(c109.258,93.325) 109.783,94.625 cw(c109.258,93.325) 109.789,94.622 ; 109.631,94.676 109.789,94.676 ; 109.789,62.932 109.789,63.18 ; 109.789,62.932 110.297,62.932 ; 109.789,63.18 109.789,63.688 ; 109.789,63.18 110.297,63.18 ; 109.789,63.688 109.789,64.196 ; 109.789,63.688 110.297,63.688 ; 109.789,64.196 109.789,64.704 ; 109.789,64.196 110.297,64.196 ; 109.789,64.704 109.789,65.212 ; 109.789,64.704 110.297,64.704 ; 109.789,65.212 109.789,65.72 ; 109.789,65.212 110.297,65.212 ; 109.789,65.72 109.789,66.228 ; 109.789,65.72 110.297,65.72 ; 109.789,66.228 109.789,66.736 ; 109.789,66.228 110.297,66.228 ; 109.789,66.736 109.789,67.244 ; 109.789,66.736 110.297,66.736 ; 109.789,67.244 C28.2@109.789,67.752 ; 109.789,67.244 110.297,67.244 ; C28.2@109.789,67.752 C28.2@109.789,68.26 ; C28.2@109.789,67.752 C28.2@110.297,67.752 ; C28.2@109.789,68.26 C28.2@109.789,68.311 C28.2@109.789,68.768 ; C28.2@109.789,68.26 C28.2@110.297,68.26 ; C28.2@109.789,68.768 109.789,69.276 ; C28.2@109.789,68.768 C28.2@110.297,68.768 ; 109.789,69.276 109.789,69.548 ; 109.789,69.276 110.297,69.276 ; 109.789,69.548 110.297,69.548 ; 109.789,75.835 109.789,75.849 109.789,75.88 ; 109.789,75.835 110.297,75.835 ; 109.789,75.88 109.789,76.007 109.789,76.388 ; 109.789,75.88 110.297,75.88 ; 109.789,76.388 110.297,76.388 ; 109.789,76.388 109.789,76.445 ; 109.789,76.445 110.297,76.445 ; 109.789,80.234 109.789,80.452 ; 109.789,80.234 109.789,80.452 ; 109.789,80.452 109.789,80.96 ; 109.789,80.452 109.789,80.96 ; 109.789,80.96 109.789,81.468 ; 109.789,80.96 109.789,81.468 ; 109.789,81.468 109.789,81.976 ; 109.789,81.468 109.789,81.976 ; 109.789,81.976 109.789,82.484 ; 109.789,81.976 109.789,82.484 ; 109.789,82.484 109.789,82.992 ; 109.789,82.484 109.789,82.992 ; 109.789,82.992 109.789,83.5 ; 109.789,82.992 109.789,83.5 ; 109.789,83.5 109.789,84.008 ; 109.789,83.5 109.789,84.008 ; 109.789,84.008 109.789,84.516 ; 109.789,84.008 109.789,84.516 ; 109.789,84.516 109.789,85.024 ; 109.789,84.516 109.789,85.024 ; 109.789,85.024 109.789,85.532 ; 109.789,85.024 109.789,85.532 ; 109.789,85.532 109.789,86.04 ; 109.789,85.532 109.789,86.04 ; 109.789,86.04 109.789,86.548 ; 109.789,86.04 109.789,86.421 109.916,86.548 ; 109.789,86.548 109.916,86.548 ; 109.789,86.548 109.789,86.566 ; 109.789,86.566 109.934,86.566 109.916,86.548 ; 109.789,94.622 cw(c109.258,93.325) 110.297,94.266 ; 109.789,94.622 109.789,94.676 ; 109.789,94.676 110.297,94.676 ; 109.789,94.676 109.789,95.184 ; 109.789,95.184 109.789,95.692 ; 109.789,95.184 110.297,95.184 ; 109.789,95.692 109.789,95.946 ; 109.789,95.692 110.297,95.692 ; 109.789,95.946 110.297,95.946 ; 110.297,62.932 110.297,63.18 ; 110.297,62.932 110.805,62.932 ; 110.297,63.18 110.297,63.688 ; 110.297,63.18 110.805,63.18 ; 110.297,63.688 110.297,64.196 ; 110.297,63.688 110.805,63.688 ; 110.297,64.196 110.297,64.704 ; 110.297,64.196 110.805,64.196 ; 110.297,64.704 110.297,65.212 ; 110.297,64.704 110.805,64.704 ; 110.297,65.212 110.297,65.72 ; 110.297,65.212 110.805,65.212 ; 110.297,65.72 110.297,66.228 ; 110.297,65.72 110.805,65.72 ; 110.297,66.228 110.297,66.736 ; 110.297,66.228 110.805,66.228 ; 110.297,66.736 110.297,67.244 ; 110.297,66.736 110.805,66.736 ; 110.297,67.244 C28.2@110.297,67.752 ; 110.297,67.244 110.805,67.244 ; C28.2@110.297,67.752 C28.2@110.297,68.26 ; C28.2@110.297,67.752 110.805,67.752 ; C28.2@110.297,68.26 110.805,68.26 ; C28.2@110.297,68.26 C28.2@110.297,68.768 ; C28.2@110.297,68.768 110.297,69.276 ; C28.2@110.297,68.768 110.805,68.768 ; 110.297,69.276 110.297,69.548 ; 110.297,69.276 110.805,69.276 ; 110.297,69.548 110.805,69.548 ; 110.297,75.835 110.297,75.849 110.297,75.88 ; 110.297,75.835 110.805,75.835 ; 110.297,75.88 110.297,76.007 110.297,76.388 ; 110.297,75.88 110.805,75.88 ; 110.297,76.388 110.41,76.388 ; 110.297,76.388 110.297,76.445 ; 110.297,76.445 110.353,76.445 110.41,76.388 ; 110.297,94.266 110.297,94.676 ; 110.297,94.676 110.297,95.184 ; 110.297,94.676 110.805,94.676 ; 110.297,95.184 110.297,95.692 ; 110.297,95.184 110.805,95.184 ; 110.297,95.692 110.297,95.946 ; 110.297,95.692 110.805,95.692 ; 110.297,95.946 110.805,95.946 ; 110.41,76.388 110.707,76.091 ; 110.626,93.02 110.783,92.863 ; 110.697,93.66 ccw(c112.075,93.406) 110.695,93.649 ccw(c112.075,93.406) 110.783,92.863 ; 110.707,76.091 ccw(c111.222,76.606) 110.805,76.009 ; 110.707,76.091 ccw(c111.222,76.606) 110.805,76.009 ; 110.805,62.932 111.313,62.932 ; 110.805,62.932 110.805,63.18 ; 110.805,63.18 110.805,63.688 ; 110.805,63.18 111.313,63.18 ; 110.805,63.688 110.805,64.196 ; 110.805,63.688 111.313,63.688 ; 110.805,64.196 110.805,64.704 ; 110.805,64.196 111.313,64.196 ; 110.805,64.704 110.805,65.212 ; 110.805,64.704 111.313,64.704 ; 110.805,65.212 111.313,65.212 ; 110.805,65.212 110.805,65.72 ; 110.805,65.72 111.313,65.72 ; 110.805,65.72 110.805,66.228 ; 110.805,66.228 111.313,66.228 ; 110.805,66.228 110.805,66.736 ; 110.805,66.736 110.805,67.244 ; 110.805,66.736 111.313,66.736 ; 110.805,67.244 110.805,67.752 ; 110.805,67.244 111.313,67.244 ; 110.805,67.752 111.313,67.752 ; 110.805,67.752 110.805,68.26 ; 110.805,68.26 110.805,68.768 ; 110.805,68.26 111.313,68.26 ; 110.805,68.768 111.313,68.768 ; 110.805,68.768 110.805,69.276 ; 110.805,69.276 111.299,69.276 ; 110.805,69.276 110.805,69.548 ; 110.805,75.835 110.805,75.849 110.805,75.88 ; 110.805,75.88 110.805,76.007 110.805,76.009 ; 110.805,75.88 111.161,75.88 ; 110.805,76.009 ccw(c111.222,76.606) 110.807,76.007 ; 110.805,76.009 ccw(c111.222,76.606) 110.807,76.007 ; 110.805,94.168 110.805,94.676 ; 110.805,94.168 110.805,93.999 cw(c112.075,93.406) 110.899,94.168 ; 110.805,94.168 110.899,94.168 ; 110.805,94.676 111.313,94.676 ; 110.805,94.676 110.805,95.184 ; 110.805,95.184 110.805,95.692 ; 110.805,95.184 111.313,95.184 ; 110.805,95.692 110.805,95.946 ; 110.805,95.692 111.313,95.692 ; 110.805,95.946 111.313,95.946 ; 110.807,76.007 ccw(c111.222,76.606) 111.161,75.88 ; 110.807,76.007 ccw(c111.222,76.606) 111.161,75.88 ; 111.161,75.88 ccw(c111.222,76.606) 111.222,75.877 ; 111.161,75.88 ccw(c111.222,76.606) 111.222,75.877 ; 111.179,69.396 cw(c111.694,69.911) 111.039,69.592 ccw(c111.694,69.911) 111.179,69.396 ; 111.179,69.396 111.299,69.276 ; 111.299,69.276 111.313,69.262 ; 111.313,62.932 111.821,62.932 ; 111.313,62.932 111.313,63.18 ; 111.313,63.18 111.313,63.688 ; 111.313,63.18 111.821,63.18 ; 111.313,63.688 111.313,64.196 ; 111.313,63.688 111.821,63.688 ; 111.313,64.196 111.313,64.704 ; 111.313,64.196 111.821,64.196 ; 111.313,64.704 111.313,65.212 ; 111.313,64.704 111.821,64.704 ; 111.313,65.212 111.313,65.72 ; 111.313,65.212 111.821,65.212 ; 111.313,65.72 111.313,66.228 ; 111.313,65.72 111.821,65.72 ; 111.313,66.228 111.821,66.228 ; 111.313,66.228 111.313,66.736 ; 111.313,66.736 111.313,67.244 ; 111.313,66.736 111.821,66.736 ; 111.313,67.244 111.313,67.752 ; 111.313,67.244 111.821,67.244 ; 111.313,67.752 111.821,67.752 ; 111.313,67.752 111.313,68.26 ; 111.313,68.26 111.313,68.768 ; 111.313,68.26 111.821,68.26 ; 111.313,68.768 111.313,69.262 ; 111.313,68.768 111.807,68.768 ; 111.313,69.262 111.807,68.768 ; 111.313,94.676 111.313,95.184 ; 111.313,94.676 111.482,94.676 ; 111.313,95.184 pad.@111.821,95.184 ; 111.313,95.184 111.313,95.692 ; 111.313,95.692 111.313,95.946 ; 111.313,95.692 pad.@111.821,95.692 ; 111.313,95.946 111.821,95.946 ; 111.482,94.676 cw(c112.075,93.406) 111.821,94.784 ; 111.807,68.768 111.821,68.754 ; 111.821,62.932 112.329,62.932 ; 111.821,62.932 111.821,63.18 ; 111.821,63.18 111.821,63.688 ; 111.821,63.18 112.329,63.18 ; 111.821,63.688 111.821,64.196 ; 111.821,63.688 112.329,63.688 ; 111.821,64.196 111.821,64.704 ; 111.821,64.196 112.329,64.196 ; 111.821,64.704 111.821,65.212 ; 111.821,64.704 112.329,64.704 ; 111.821,65.212 111.821,65.72 ; 111.821,65.212 112.329,65.212 ; 111.821,65.72 111.821,66.228 ; 111.821,65.72 112.329,65.72 ; 111.821,66.228 112.329,66.228 ; 111.821,66.228 111.821,66.736 ; 111.821,66.736 111.821,67.244 ; 111.821,66.736 112.329,66.736 ; 111.821,67.244 111.821,67.752 ; 111.821,67.244 112.329,67.244 ; 111.821,67.752 112.329,67.752 ; 111.821,67.752 111.821,68.26 ; 111.821,68.26 111.821,68.754 ; 111.821,68.26 112.018,68.26 ; 111.821,94.784 pad.@111.821,95.184 ; pad.@111.821,95.184 112.329,95.184 ; pad.@111.821,95.184 pad.@111.821,95.692 ; pad.@111.821,95.692 111.821,95.946 ; pad.@111.821,95.692 112.329,95.692 ; 111.821,95.946 112.329,95.946 ; 112.018,68.26 ccw(c112.851,68.781) 112.329,67.949 ; 112.329,62.932 pad.@112.837,62.932 ; 112.329,62.932 112.329,63.18 ; 112.329,63.18 112.329,63.688 ; 112.329,63.18 pad.@112.837,63.18 ; 112.329,63.688 112.329,64.196 ; 112.329,63.688 112.837,63.688 ; 112.329,64.196 112.329,64.704 ; 112.329,64.196 112.837,64.196 ; 112.329,64.704 112.329,65.212 ; 112.329,64.704 112.837,64.704 ; 112.329,65.212 112.837,65.212 ; 112.329,65.212 112.329,65.72 ; 112.329,65.72 112.837,65.72 ; 112.329,65.72 112.329,66.228 ; 112.329,66.228 112.837,66.228 ; 112.329,66.228 112.329,66.736 ; 112.329,66.736 112.329,67.244 ; 112.329,66.736 112.837,66.736 ; 112.329,67.244 112.329,67.752 ; 112.329,67.244 112.837,67.244 ; 112.329,67.752 112.837,67.752 ; 112.329,67.752 112.329,67.949 ; 112.329,67.949 ccw(c112.851,68.781) 112.331,67.948 ccw(c112.851,68.781) 112.837,67.798 ; 112.329,95.184 112.329,95.692 ; 112.329,95.184 112.837,95.184 ; 112.329,95.692 112.329,95.946 ; 112.329,95.692 112.837,95.692 ; 112.329,95.946 112.837,95.946 ; 112.668,94.676 cw(c112.075,93.406) 112.837,94.582 ; 112.668,94.676 112.837,94.676 ; pad.@112.837,62.932 pad.@112.837,63.18 ; pad.@112.837,62.932 113.345,62.932 ; pad.@112.837,63.18 pad.@113.345,63.18 ; pad.@112.837,63.18 112.837,63.688 ; 112.837,63.688 112.837,64.196 ; 112.837,63.688 113.345,63.688 ; 112.837,64.196 112.837,64.704 ; 112.837,64.196 113.345,64.196 ; 112.837,64.704 112.837,65.212 ; 112.837,64.704 113.345,64.704 ; 112.837,65.212 113.345,65.212 ; 112.837,65.212 112.837,65.72 ; 112.837,65.72 112.837,66.228 ; 112.837,65.72 113.345,65.72 ; 112.837,66.228 112.837,66.736 ; 112.837,66.228 113.339,66.228 ; 112.837,66.736 112.837,67.244 ; 112.837,67.244 112.837,67.752 ; 112.837,67.244 113.345,67.244 ; 112.837,67.752 113.345,67.752 ; 112.837,67.752 112.837,67.798 ; 112.837,67.798 ccw(c112.851,68.781) 113.343,67.93 ccw(c112.851,68.781) 113.345,67.931 ; 112.837,94.582 cw(c112.075,93.406) 112.838,94.581 cw(c112.075,93.406) 113.172,94.278 ; 112.837,94.582 112.837,94.676 ; 112.837,94.676 113.345,94.676 ; 112.837,94.676 112.837,95.184 ; 112.837,95.184 112.837,95.692 ; 112.837,95.184 113.345,95.184 ; 112.837,95.692 112.837,95.946 ; 112.837,95.692 113.345,95.692 ; 112.837,95.946 113.345,95.946 ; 113.172,94.278 113.345,94.45 ; 113.339,66.228 ccw(c114.245,66.61) 113.345,66.215 ; 113.345,62.932 113.853,62.932 ; 113.345,62.932 pad.@113.345,63.18 ; pad.@113.345,63.18 113.853,63.18 ; pad.@113.345,63.18 113.345,63.688 ; 113.345,63.688 113.345,64.196 ; 113.345,63.688 113.853,63.688 ; 113.345,64.196 113.345,64.704 ; 113.345,64.196 113.853,64.196 ; 113.345,64.704 113.345,65.212 ; 113.345,64.704 113.853,64.704 ; 113.345,65.212 113.853,65.212 ; 113.345,65.212 113.345,65.72 ; 113.345,65.72 113.828,65.72 ; 113.345,65.72 113.345,66.215 ; 113.345,66.215 ccw(c114.245,66.61) 113.828,65.72 ; 113.345,67.005 113.345,67.244 ; 113.345,67.244 113.345,67.752 ; 113.345,67.752 113.853,67.752 ; 113.345,67.752 113.345,67.931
